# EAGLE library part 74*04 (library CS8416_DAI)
Hex INVERTER
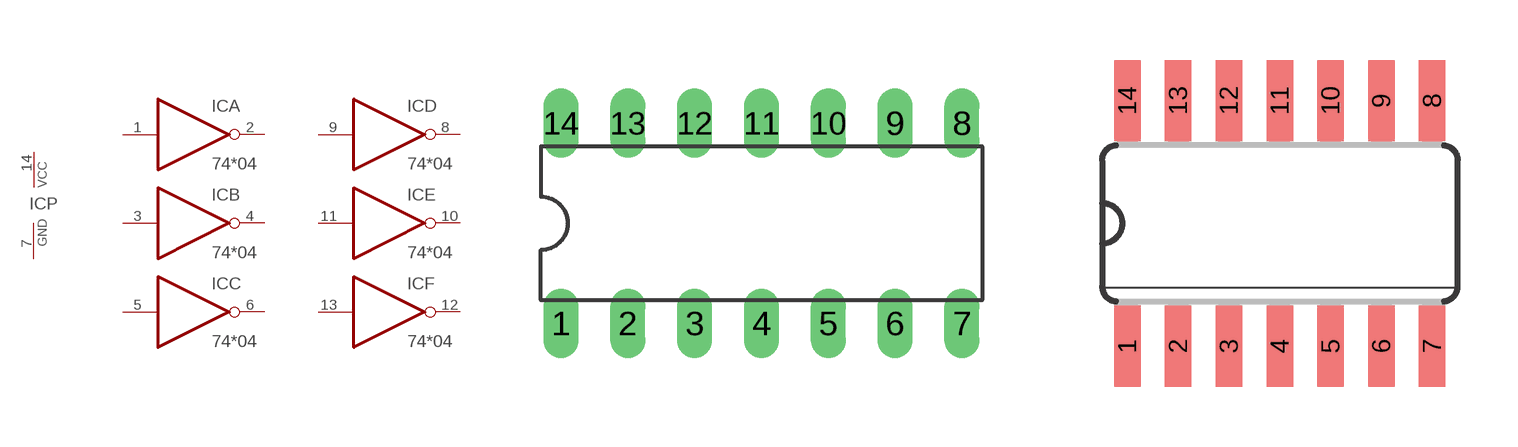
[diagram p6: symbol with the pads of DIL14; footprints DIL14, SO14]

Designator prefix IC; gates A=7404 B=7404 C=7404 D=7404 E=7404 F=7404 P=PWRN

## 7404N, 74AC04N, 74ACT04N, 74ALS04N, 74AS04N, 74HC04N, 74HCT04N, 74LS04N, 74S04N  [DIL14]
1  A:I  in
2  A:O  out
3  B:I  in
4  B:O  out
5  C:I  in
6  C:O  out
7  P:GND  pwr
8  D:O  out
9  D:I  in
10  E:O  out
11  E:I  in
12  F:O  out
13  F:I  in
14  P:VCC  pwr

## 7404D, 74AC04D, 74ACT04D, 74ALS04D, 74AS04D, 74HC04D, 74HCT04D, 74LS04D, 74S04D  [SO14]
Pads as for DIL14

## 7404FK, 74AC04FK, 74ACT04FK, 74HC04FK, 74HCT04FK, 74LS04FK, 74S04FK  [LCC20]
2  A:I  in
3  A:O  out
4  B:I  in
6  B:O  out
8  C:I  in
9  C:O  out
10  P:GND  pwr
12  D:O  out
13  D:I  in
14  E:O  out
16  E:I  in
18  F:O  out
19  F:I  in
20  P:VCC  pwr

## Footprint DIL14 (pad centres in mm)
Dual In Line Package
drill 0.813 long: 1 -7.62,-3.81; 2 -5.08,-3.81; 3 -2.54,-3.81; 4 0,-3.81; 5 2.54,-3.81; 6 5.08,-3.81; 7 7.62,-3.81; 8 7.62,3.81; 9 5.08,3.81; 10 2.54,3.81; 11 0,3.81; 12 -2.54,3.81; 13 -5.08,3.81; 14 -7.62,3.81

## Footprint SO14 (pad centres in mm)
Small Outline package 150 mil
smd 0.66 x 2.032: 1 -3.81,-3.073; 2 -2.54,-3.073; 3 -1.27,-3.073; 4 0,-3.073; 5 1.27,-3.073; 6 2.54,-3.073; 7 3.81,-3.073; 8 3.81,3.073; 9 2.54,3.073; 10 1.27,3.073; 11 0,3.073; 12 -1.27,3.073; 13 -2.54,3.073; 14 -3.81,3.073

## Footprint LCC20 (pad centres in mm)
Leadless Chip Carrier Ceramic Package
smd 0.8 x 3.4: 1 0,3.8
smd 0.8 x 2: 2 -1.27,4.5; 3 -2.54,4.5; 9 -2.54,-4.5; 10 -1.27,-4.5; 11 0,-4.5; 12 1.27,-4.5; 13 2.54,-4.5; 19 2.54,4.5; 20 1.27,4.5
smd 2 x 0.8: 4 -4.5,2.54; 5 -4.5,1.27; 6 -4.5,0; 7 -4.5,-1.27; 8 -4.5,-2.54; 14 4.5,-2.54; 15 4.5,-1.27; 16 4.5,0; 17 4.5,1.27; 18 4.5,2.54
